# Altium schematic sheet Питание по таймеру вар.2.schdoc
size 148 x 127 mm
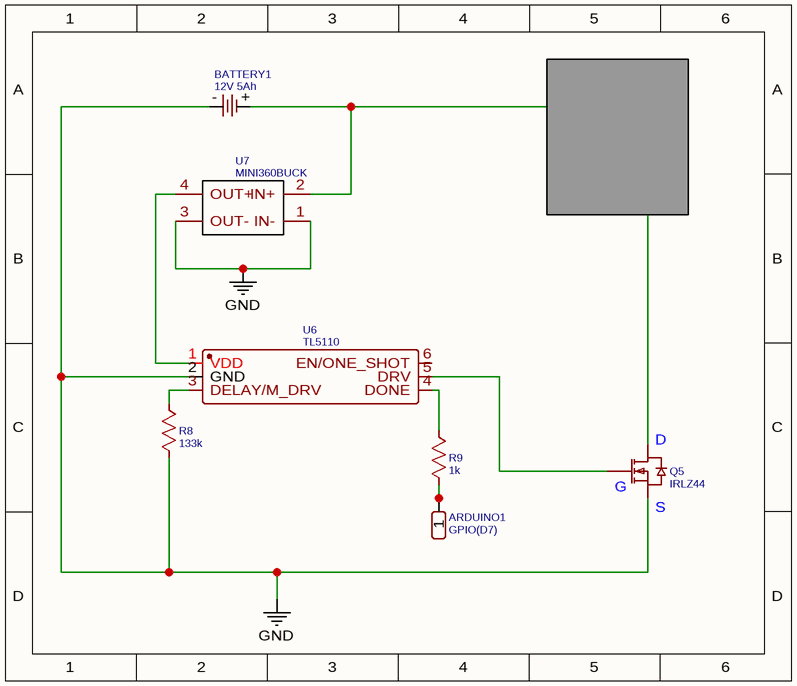
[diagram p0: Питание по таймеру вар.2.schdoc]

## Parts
ARDUINO1  GPIO(D7)  [HDR-M-2.54_1X1]
BATTERY1  12V 5Ah  [BATTERY-SMD-MY-2032]
Q5  IRLZ44  [TO-220-3_L10.0-W4.5-P2.54-T]
R8  133k  [R0603]
R9  1k  [R0603]
U6  TL5110  [TSOT-23-6_L2.9-W1.6-P0.95-LS2.8-BR]
U7  MINI360BUCK  [MINI360BUCK]

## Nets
GND: BATTERY1.-(BAT+) Q5.3(S) R8.2 U6.2(GND) U7.1(IN-) U7.3(OUT-)
NetARDUINO1_1: ARDUINO1.1 R9.2
NetBATTERY1_+: BATTERY1.+(BAT-) U7.2(IN+)
NetQ5_1: Q5.1(G) U6.5(DRV)
NetR8_1: R8.1 U6.3(DELAY/M_DRV)
NetR9_1: R9.1 U6.4(DONE)
NetU6_1: U6.1(VDD) U7.4(OUT+)

Not connected (* = marked no-connect by the designer): Q5 2(D); U6 6(EN/ONE_SHOT)

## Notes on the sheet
- (+)
- Pyload
- (-)
- (near Q5) G
- (near Q5) D
- (near Q5) S

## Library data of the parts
ARDUINO1 = GPIO(D7): Contributor: LCEDA_Lib
BATTERY1 = 12V 5Ah: Manufacturer: MYOUNG(美阳); Manufacturer Part: MY-2032-10; Contributor: lcsc
Q5 = IRLZ44: Manufacturer: Infineon(英飞凌); Manufacturer Part: IRLZ44NPBF
R8 = 133k: nameAlias: Value(Ω); Contributor: LCEDA_Lib
R9 = 1k: nameAlias: Value(Ω); Contributor: LCEDA_Lib
U6 = TL5110: Manufacturer: TI(德州仪器); Manufacturer Part: TPL5110DDCR; Contributor: lcsc; nameAlias: Value
U7 = MINI360BUCK: Contributor: Andrey Fedorov; sourceId: FRLFXR8qI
